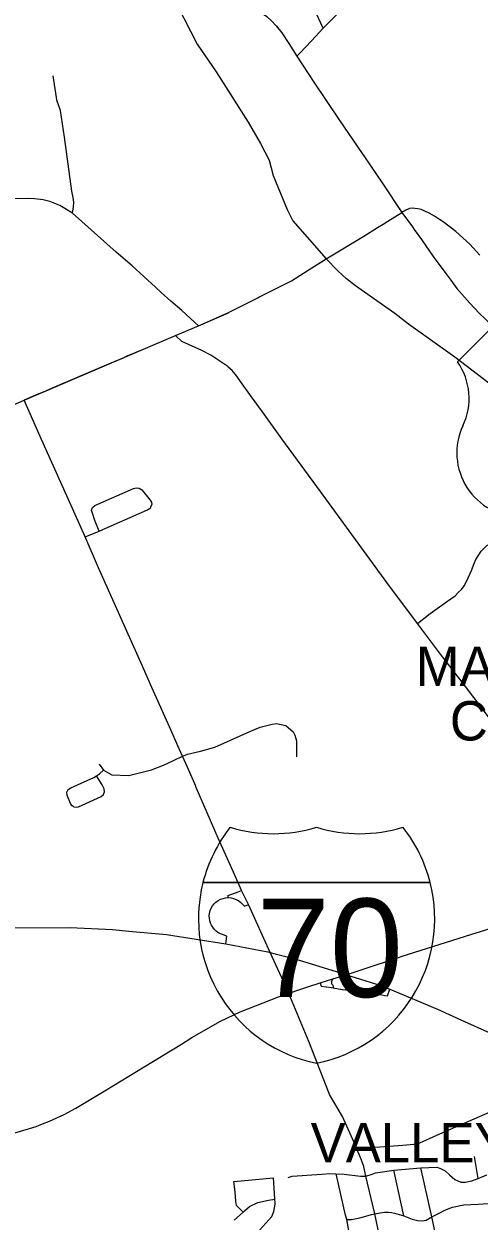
# Model space of a CAD drawing. Extents: x 1755200 to 1902939, y 644115 to 788070.
# Drawn here: x 1802380 to 1808159, y 715838 to 731049 of the extents above; entities that cross this region are included whole.
import ezdxf

# ---------------------------------------------------------------- set-up
doc = ezdxf.new("R2010")
doc.units = 0
for name, color, linetype in [('GM_X_City_Street', 7, 'Continuous'), ('GM_X_Corporation_Text', 7, 'Continuous'), ('GM_X_County_Road', 7, 'Continuous'), ('GM_X_Interchange_Ramps', 7, 'Continuous'), ('GM_X_Interstate_Route', 7, 'Continuous'), ('GM_X_Interstate_Shield', 7, 'Continuous'), ('GM_X_Township', 7, 'Continuous'), ('GM_X_US_Route', 7, 'Continuous'), ('GM_X_US_Shield', 7, 'Continuous')]:
    doc.layers.add(name, color=color, linetype=linetype)

msp = doc.modelspace()

# ---------------------------------------------------------------- linework, layer by layer
at = {"layer": 'GM_X_City_Street'}
for points in [[(1806181, 730993), (1806089, 731187), (1805956, 731446), (1805726, 731959), (1805719, 731978), (1805699, 732037), (1805670, 732113), (1805670, 732117), (1805665, 732193), (1805680, 732287), (1805707, 732373), (1805773, 732532), (1805833, 732699), (1805895, 732898), (1805900, 732934), (1805901, 732942), (1805923, 733275), (1805947, 733624), (1805947, 733627), (1805948, 733644), (1805950, 733709)], [(1805882, 730679), (1806030, 730834), (1806181, 730993), (1806579, 731391)], [(1805845, 730641), (1805882, 730679)], [(1802792, 730114), (1802752, 730391)], [(1802801, 730069), (1802797, 730080), (1802792, 730114)], [(1802995, 728645), (1803009, 728724), (1803012, 728782), (1803003, 728845), (1802986, 728923), (1802896, 729610), (1802844, 729950), (1802801, 730069)], [(1804051, 727704), (1803752, 727975), (1803549, 728149), (1802995, 728645), (1802837, 728740), (1802710, 728791), (1802622, 728814), (1802519, 728827), (1802421, 728830), (1802259, 728826)], [(1807002, 728543), (1807179, 728652)], [(1808171, 728109), (1808042, 728250), (1807866, 728411), (1807702, 728534), (1807655, 728565), (1807593, 728605), (1807524, 728646), (1807422, 728689), (1807380, 728699), (1807342, 728705), (1807310, 728707), (1807276, 728703), (1807231, 728683), (1807179, 728652)], [(1806160, 728026), (1806217, 728062), (1806697, 728354), (1806869, 728461)], [(1806869, 728461), (1806942, 728505), (1807002, 728543)], [(1805718, 727755), (1805777, 727785), (1806037, 727949), (1806160, 728026)], [(1804595, 727213), (1804383, 727406), (1804247, 727528), (1804124, 727638), (1804051, 727704)], [(1804976, 727380), (1804979, 727381), (1805718, 727755)], [(1804595, 727213), (1804976, 727380)], [(1803634, 726804), (1803692, 726830), (1803896, 726917), (1804305, 727091)], [(1804305, 727091), (1804595, 727213)], [(1804975, 726686), (1804967, 726694), (1804894, 726746), (1804751, 726838), (1804640, 726900), (1804386, 727015), (1804305, 727091)], [(1808795, 721558), (1808779, 721581), (1808599, 721824), (1808306, 722209), (1807985, 722632), (1807671, 723039), (1807378, 723432), (1806990, 723953), (1806147, 725108), (1805654, 725776), (1805410, 726118), (1805269, 726310), (1805131, 726507), (1805081, 726574), (1805022, 726645), (1804975, 726686)], [(1802388, 726272), (1802531, 726334)], [(1802627, 726374), (1802771, 726436)], [(1803334, 724604), (1803280, 724739), (1803249, 724831), (1803239, 724869), (1803252, 724905), (1803281, 724930), (1803770, 725145), (1803806, 725155), (1803843, 725150), (1803875, 725131), (1803983, 724999), (1803999, 724972), (1804004, 724941)], [(1803342, 724607), (1803948, 724873), (1803985, 724900), (1804004, 724941)], [(1807378, 723432), (1807538, 723556), (1807745, 723707), (1807857, 723784), (1807900, 723827), (1807937, 723862), (1807970, 723910), (1807999, 723964), (1808064, 724102), (1808097, 724193), (1808119, 724243), (1808185, 724351), (1808258, 724422), (1808355, 724470), (1808443, 724499), (1808549, 724510), (1808649, 724530), (1808744, 724574), (1808864, 724658)], [(1803156, 724530), (1803334, 724604), (1803342, 724607)], [(1803335, 721645), (1803388, 721569), (1803496, 721509), (1803710, 721500), (1803999, 721571), (1804151, 721631), (1804198, 721653), (1804395, 721743), (1804458, 721769), (1804622, 721810), (1804803, 721861), (1805004, 721950), (1805250, 722058), (1805379, 722113), (1805530, 722153), (1805588, 722161), (1805706, 722134), (1805797, 722054), (1805820, 722013), (1805839, 721941), (1805840, 721841), (1805839, 721736)], [(1804548, 721394), (1804436, 721651), (1804395, 721743), (1804352, 721838), (1804227, 722119)], [(1803014, 721101), (1802992, 721115), (1802976, 721136), (1802927, 721245), (1802925, 721286), (1802943, 721322), (1802977, 721344), (1803268, 721474), (1803301, 721497), (1803339, 721522), (1803388, 721569)], [(1803014, 721101), (1803042, 721096), (1803071, 721103), (1803362, 721234), (1803391, 721257), (1803403, 721292), (1803397, 721329), (1803372, 721379), (1803301, 721497)], [(1805165, 719995), (1805143, 720040)], [(1805700, 718825), (1805505, 719251), (1805231, 719861), (1805165, 719995)], [(1807147, 719191), (1807170, 719199), (1807985, 719456), (1809018, 719781), (1809437, 719926)], [(1806650, 719027), (1806676, 719035), (1807147, 719191)], [(1805936, 718796), (1805996, 718817), (1806141, 718863), (1806302, 718914), (1806471, 718968), (1806533, 718988), (1806650, 719027)], [(1806605, 716759), (1807192, 716801), (1807332, 716813), (1807406, 716833), (1807662, 716944), (1808163, 717165), (1809059, 717554), (1809064, 717556), (1809453, 717726), (1809714, 717849), (1809933, 717932), (1810065, 717987), (1810703, 718260)], [(1806608, 716750), (1806605, 716759), (1806424, 717166), (1806262, 717446), (1806257, 717458)], [(1807019, 715006), (1806926, 715501), (1806913, 715566), (1806834, 715930), (1806723, 716408), (1806694, 716533), (1806665, 716613), (1806648, 716652)], [(1808147, 716377), (1808100, 716657)], [(1805735, 716390), (1805784, 716410), (1806164, 716433), (1806262, 716443)], [(1806262, 716443), (1806346, 716437), (1806445, 716433), (1806655, 716408), (1806723, 716408), (1806802, 716435), (1806845, 716451), (1807077, 716484), (1807420, 716515), (1807623, 716524), (1807670, 716505), (1807728, 716477), (1807785, 716425), (1807852, 716365), (1807927, 716333), (1807989, 716333), (1808069, 716349), (1808147, 716377), (1808258, 716424)], [(1806479, 715858), (1806463, 715912), (1806346, 716437)], [(1807203, 715903), (1807077, 716484)], [(1807635, 715469), (1807608, 715540), (1807599, 715606), (1807592, 715665), (1807592, 715730), (1807581, 715794), (1807559, 715890), (1807420, 716515)], [(1805044, 716341), (1805550, 716387)], [(1805162, 715949), (1805080, 716036), (1805069, 716088), (1805060, 716209), (1805044, 716341)], [(1805569, 716069), (1805566, 716113), (1805566, 716118), (1805562, 716188), (1805550, 716387)], [(1805050, 715848), (1805162, 715949), (1805182, 715967), (1805244, 716022), (1805349, 716075), (1805486, 716105), (1805566, 716118)], [(1805350, 715557), (1805329, 715602), (1805342, 715656), (1805377, 715725), (1805526, 715896), (1805555, 715958), (1805570, 716054), (1805569, 716069)], [(1806795, 715920), (1806834, 715930), (1806904, 715944), (1806960, 715951), (1807011, 715952), (1807047, 715948), (1807085, 715936), (1807203, 715903), (1807311, 715863), (1807379, 715846), (1807447, 715841), (1807486, 715850), (1807559, 715890), (1807651, 715939), (1807726, 715976), (1807823, 716013), (1807967, 716042), (1808146, 716054), (1808338, 716066), (1808432, 716056), (1808558, 716030)], [(1806479, 715858), (1806539, 715859), (1806647, 715880), (1806779, 715915), (1806795, 715920)], [(1806524, 715667), (1806508, 715692), (1806479, 715858), (1806479, 715858)]]:
    msp.add_lwpolyline(points, dxfattribs=at)
at = {"layer": 'GM_X_County_Road'}
for points in [[(1803538, 726763), (1803547, 726767), (1803634, 726804)], [(1802771, 726436), (1803001, 726534), (1803487, 726742), (1803538, 726763)], [(1802531, 726334), (1802627, 726374)], [(1799141, 724852), (1799900, 725183), (1800858, 725605), (1802383, 726270), (1802388, 726272)], [(1804227, 722119), (1803988, 722657), (1803883, 722890), (1803328, 724138), (1803156, 724530), (1802942, 725014), (1802587, 725805), (1802383, 726270)], [(1805143, 720040), (1805040, 720271), (1804846, 720701), (1804568, 721347), (1804557, 721374), (1804548, 721394)], [(1802491, 717028), (1802534, 717041), (1802615, 717072), (1802702, 717105), (1802889, 717191), (1803040, 717273), (1803418, 717499), (1803907, 717797), (1804381, 718087), (1804511, 718168), (1804874, 718376), (1805124, 718495), (1805613, 718685), (1805743, 718731), (1805834, 718762)], [(1805743, 718731), (1805700, 718825)], [(1806257, 717458), (1805996, 718119), (1805743, 718731)], [(1805834, 718762), (1805936, 718796)], [(1801756, 716859), (1801874, 716872), (1801993, 716892), (1802093, 716911), (1802251, 716955), (1802491, 717028)], [(1806648, 716652), (1806636, 716683), (1806608, 716750)]]:
    msp.add_lwpolyline(points, dxfattribs=at)
at = {"layer": 'GM_X_Interchange_Ramps'}
for points in [[(1804944, 719361), (1804958, 719458), (1804930, 719467), (1804901, 719478), (1804874, 719489), (1804842, 719506), (1804820, 719523), (1804798, 719543), (1804777, 719570), (1804760, 719596), (1804748, 719623), (1804739, 719654), (1804734, 719686), (1804733, 719717), (1804736, 719747), (1804745, 719782), (1804758, 719813), (1804775, 719843), (1804794, 719867), (1804818, 719890), (1804846, 719910), (1804875, 719926), (1804910, 719938), (1804941, 719944), (1804973, 719947), (1805010, 719943), (1805042, 719936), (1805076, 719923), (1805107, 719905), (1805132, 719885), (1805180, 719838), (1805231, 719861)], [(1804973, 719947), (1804975, 719974), (1805100, 720020), (1805143, 720040)], [(1806302, 718914), (1806286, 718887), (1806286, 718857), (1806291, 718848), (1806296, 718840), (1806301, 718833), (1806308, 718827), (1806305, 718803)], [(1806141, 718863), (1806155, 718821), (1806283, 718805), (1806305, 718803), (1806419, 718782), (1806591, 718762), (1806639, 718755), (1806681, 718749), (1806734, 718741), (1806780, 718734), (1806827, 718726), (1806877, 718718), (1806923, 718711), (1806961, 718704), (1806995, 718699), (1807027, 718784)]]:
    msp.add_lwpolyline(points, dxfattribs=at)
at = {"layer": 'GM_X_Interstate_Route'}
for points in [[(1801787, 719615), (1802007, 719584), (1802264, 719565), (1802968, 719566), (1803502, 719542), (1803711, 719521), (1804191, 719479), (1804944, 719361), (1805475, 719257)], [(1805475, 719257), (1805505, 719251), (1805571, 719235)], [(1805571, 719235), (1805809, 719174)], [(1805809, 719174), (1805821, 719171), (1806123, 719075), (1806414, 718986), (1806471, 718968), (1806531, 718949), (1806655, 718911)], [(1806655, 718911), (1806844, 718852), (1807027, 718784), (1807630, 718532), (1807973, 718373), (1808709, 718045), (1809282, 717799)]]:
    msp.add_lwpolyline(points, dxfattribs=at)
at = {"layer": 'GM_X_Interstate_Shield'}
for p, q in [((1804653, 720138), (1807539, 720138)), ((1807539, 720138), (1804653, 720138)), ((1807539, 720138), (1804653, 720138))]:
    msp.add_line(p, q, dxfattribs=at)
for centre, start, end in [((1806471, 719679), 141.669, 165.8066), ((1805548, 722635), 253.0091, 286.9909), ((1806644, 722635), 253.0091, 286.9909), ((1805721, 719679), 14.1934, 38.331), ((1806471, 719679), 165.8066, 258.463), ((1805721, 719679), 281.537, 14.1934)]:
    msp.add_arc(centre, 1875, start, end, dxfattribs=at)
at = {"layer": 'GM_X_Township'}
for points in [[(1804241, 731458), (1804579, 730790), (1804820, 730439), (1805226, 729799), (1805384, 729530), (1805494, 729317), (1805543, 729124), (1805721, 728692), (1805795, 728547), (1806217, 728062)], [(1800858, 725605), (1802383, 726270), (1804305, 727091), (1804595, 727213), (1804979, 727381), (1805777, 727785), (1806037, 727949), (1806217, 728062)], [(1808428, 726375), (1807850, 726813), (1807264, 727234), (1807088, 727370), (1806592, 727720), (1806477, 727811), (1806367, 727911), (1806217, 728062)]]:
    msp.add_lwpolyline(points, dxfattribs=at)
at = {"layer": 'GM_X_US_Route'}
for points in [[(1805423, 731174), (1805465, 731142), (1805524, 731088), (1805581, 731025), (1805656, 730934), (1805745, 730801), (1805845, 730641)], [(1805845, 730641), (1806062, 730307), (1806384, 729832), (1806675, 729403)], [(1806675, 729403), (1806697, 729372), (1806936, 729017), (1807179, 728652)], [(1807179, 728652), (1807312, 728469), (1807335, 728437)], [(1807335, 728437), (1807427, 728308), (1807578, 728095), (1807738, 727876), (1807801, 727791)], [(1807801, 727791), (1807876, 727689), (1808041, 727500), (1808162, 727375), (1808242, 727298), (1808316, 727225), (1808591, 726948), (1808847, 726687), (1809000, 726517), (1809056, 726409), (1809186, 726160), (1809325, 725871), (1809418, 725683), (1809424, 725673)]]:
    msp.add_lwpolyline(points, dxfattribs=at)
at = {"layer": 'GM_X_US_Shield'}
msp.add_line((1808466, 727337), (1807886, 726757), dxfattribs=at)
for centre, start, end in [((1807221, 726291), 334.5471, 35.0009), ((1808689, 725597), 154.8319, 270.6383)]:
    msp.add_arc(centre, 812, start, end, dxfattribs=at)

# ---------------------------------------------------------------- texts
at = {"layer": 'GM_X_Corporation_Text'}
for s, p in [('MARBLE', (1807354, 722638)), ('CLIFF', (1807788, 721944)), ('VALLEYVIEW', (1806020, 716583))]:
    msp.add_text(s, height=500, rotation=0, dxfattribs=at).set_placement(p)
at = {"layer": 'GM_X_Interstate_Shield'}
msp.add_text('70', height=1250, dxfattribs=at).set_placement((1805334, 718685))

doc.saveas('drawing.dxf')
